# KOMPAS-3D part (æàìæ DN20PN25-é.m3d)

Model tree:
1. Объединить компоненты:1  (labels: СЕНС DN20PN25-В)

Referenced files in D:\Савин\!СЕНСОР\3D для заказчика\!Новый перечень\СЕНС\3. СЕНС-В\DN20\: СЕНС DN20PN25-В.a3d
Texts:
  СЕНС DN20PN25-В
  ООО НПП Сенсор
